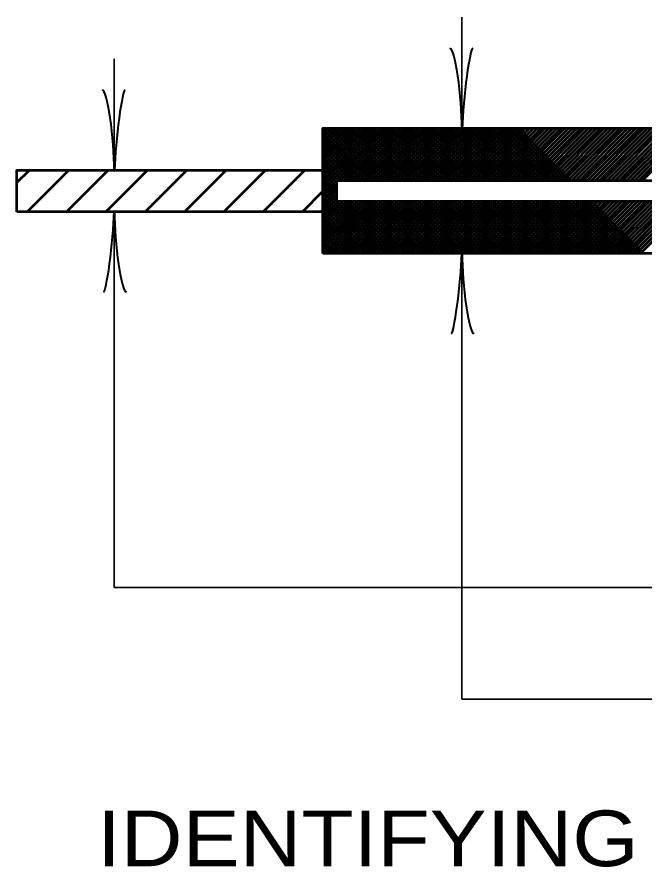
# Model space of a CAD drawing. Extents: x -1 to 679, y 0 to 440.
# Drawn here: x 282.9 to 305.44, y 121.26 to 151.8 of the extents above; entities that cross this region are included whole.
import ezdxf

# ---------------------------------------------------------------- set-up
doc = ezdxf.new("R2010")
doc.units = 0
doc.header["$LTSCALE"] = 0.8
doc.layers.add('1', color=7, linetype='Continuous', lineweight=53)

msp = doc.modelspace()

# ---------------------------------------------------------------- linework, layer by layer
at = {"layer": '1', "lineweight": 35}
for p, q in [((298.8991, 147.8013), (298.8991, 151.8013)), ((286.3991, 146.3013), (286.3991, 150.3013)), ((286.3991, 144.8013), (286.3991, 131.3013)), ((298.8991, 143.3013), (298.8991, 127.2931)), ((286.3991, 131.3013), (339.8991, 131.3013)), ((298.8991, 127.2931), (328.9684, 127.2931))]:
    msp.add_line(p, q, dxfattribs=at)
at = {"layer": '1'}
for p, q in [((293.8991, 143.3013), (293.8991, 147.8013)), ((293.8991, 147.7248), (293.9756, 147.8013)), ((293.8991, 147.5834), (294.117, 147.8013)), ((293.8991, 147.442), (294.2584, 147.8013)), ((293.8991, 147.3006), (294.3998, 147.8013)), ((293.8991, 147.1592), (294.5412, 147.8013)), ((293.8991, 147.0178), (294.6827, 147.8013)), ((293.8991, 146.8763), (294.8241, 147.8013)), ((293.8991, 146.7349), (294.9655, 147.8013)), ((293.8991, 146.5935), (295.1069, 147.8013)), ((293.8991, 146.452), (295.2484, 147.8013)), ((293.8991, 146.3106), (295.3898, 147.8013)), ((293.8991, 146.1692), (295.5312, 147.8013)), ((293.8991, 146.0277), (295.6727, 147.8013)), ((293.8991, 145.8863), (295.8141, 147.8013)), ((293.8991, 145.7449), (295.9555, 147.8013)), ((293.8991, 145.6035), (296.0969, 147.8013)), ((293.8991, 145.4621), (296.2383, 147.8013)), ((295.7336, 145.9263), (293.8991, 147.7608)), ((295.5922, 145.9263), (293.8991, 147.6194)), ((295.875, 145.9263), (294, 147.8013)), ((296.0165, 145.9263), (294.1415, 147.8013)), ((296.1579, 145.9263), (294.2829, 147.8013)), ((296.2993, 145.9263), (294.4243, 147.8013)), ((294.5048, 145.9263), (296.3798, 147.8013)), ((296.4407, 145.9263), (294.5657, 147.8013)), ((294.6462, 145.9263), (296.5212, 147.8013)), ((296.5822, 145.9263), (294.7072, 147.8013)), ((294.7876, 145.9263), (296.6626, 147.8013)), ((296.7236, 145.9263), (294.8486, 147.8013)), ((294.929, 145.9263), (296.804, 147.8013)), ((296.865, 145.9263), (294.99, 147.8013)), ((295.0704, 145.9263), (296.9454, 147.8013)), ((297.0064, 145.9263), (295.1314, 147.8013)), ((295.2118, 145.9263), (297.0868, 147.8013)), ((297.1478, 145.9263), (295.2728, 147.8013)), ((295.3533, 145.9263), (297.2283, 147.8013)), ((297.2892, 145.9263), (295.4142, 147.8013)), ((295.4947, 145.9263), (297.3697, 147.8013)), ((297.4307, 145.9263), (295.5557, 147.8013)), ((295.6361, 145.9263), (297.5111, 147.8013)), ((297.5721, 145.9263), (295.6971, 147.8013)), ((295.7775, 145.9263), (297.6525, 147.8013)), ((297.7135, 145.9263), (295.8385, 147.8013)), ((295.919, 145.9263), (297.794, 147.8013)), ((297.8549, 145.9263), (295.9799, 147.8013)), ((296.0604, 145.9263), (297.9354, 147.8013)), ((297.9963, 145.9263), (296.1213, 147.8013)), ((296.2018, 145.9263), (298.0768, 147.8013)), ((298.1377, 145.9263), (296.2627, 147.8013)), ((296.3433, 145.9263), (298.2183, 147.8013)), ((298.2792, 145.9263), (296.4042, 147.8013)), ((296.4847, 145.9263), (298.3597, 147.8013)), ((298.4207, 145.9263), (296.5457, 147.8013)), ((296.6261, 145.9263), (298.5011, 147.8013)), ((298.5621, 145.9263), (296.6871, 147.8013)), ((296.7675, 145.9263), (298.6425, 147.8013)), ((298.7035, 145.9263), (296.8285, 147.8013)), ((296.9089, 145.9263), (298.7839, 147.8013)), ((298.8449, 145.9263), (296.9699, 147.8013)), ((297.0503, 145.9263), (298.9253, 147.8013)), ((298.9863, 145.9263), (297.1113, 147.8013)), ((297.1918, 145.9263), (299.0668, 147.8013)), ((299.1277, 145.9263), (297.2527, 147.8013)), ((297.3332, 145.9263), (299.2082, 147.8013)), ((299.2692, 145.9263), (297.3942, 147.8013)), ((297.4746, 145.9263), (299.3496, 147.8013)), ((299.4106, 145.9263), (297.5356, 147.8013)), ((297.616, 145.9263), (299.491, 147.8013)), ((299.552, 145.9263), (297.677, 147.8013)), ((297.7574, 145.9263), (299.6324, 147.8013)), ((299.6934, 145.9263), (297.8184, 147.8013)), ((297.8988, 145.9263), (299.7738, 147.8013)), ((299.8348, 145.9263), (297.9598, 147.8013)), ((298.0403, 145.9263), (299.9153, 147.8013)), ((299.9762, 145.9263), (298.1012, 147.8013)), ((298.1817, 145.9263), (300.0567, 147.8013)), ((300.1177, 145.9263), (298.2427, 147.8013)), ((298.3231, 145.9263), (300.1981, 147.8013)), ((300.2591, 145.9263), (298.3841, 147.8013)), ((298.4646, 145.9263), (300.3396, 147.8013)), ((300.4005, 145.9263), (298.5255, 147.8013)), ((298.606, 145.9263), (300.481, 147.8013)), ((300.5419, 145.9263), (298.6669, 147.8013)), ((298.7474, 145.9263), (300.6224, 147.8013)), ((300.6833, 145.9263), (298.8083, 147.8013)), ((298.8888, 145.9263), (300.7638, 147.8013)), ((300.8247, 145.9263), (298.9497, 147.8013)), ((299.0302, 145.9263), (300.9052, 147.8013)), ((300.9663, 145.9263), (299.0913, 147.8013)), ((299.1717, 145.9263), (301.0467, 147.8013)), ((301.1077, 145.9263), (299.2327, 147.8013)), ((299.3131, 145.9263), (301.1881, 147.8013)), ((301.2491, 145.9263), (299.3741, 147.8013)), ((299.4545, 145.9263), (301.3295, 147.8013)), ((301.3905, 145.9263), (299.5155, 147.8013)), ((299.5959, 145.9263), (301.4709, 147.8013)), ((301.5319, 145.9263), (299.6569, 147.8013)), ((299.7373, 145.9263), (301.6123, 147.8013)), ((301.6733, 145.9263), (299.7983, 147.8013)), ((299.8787, 145.9263), (301.7537, 147.8013)), ((301.8148, 145.9263), (299.9398, 147.8013)), ((300.0202, 145.9263), (301.8952, 147.8013)), ((301.9562, 145.9263), (300.0812, 147.8013)), ((300.1616, 145.9263), (302.0366, 147.8013)), ((302.0976, 145.9263), (300.2226, 147.8013)), ((300.303, 145.9263), (302.178, 147.8013)), ((302.239, 145.9263), (300.364, 147.8013)), ((300.4444, 145.9263), (302.3194, 147.8013)), ((302.3804, 145.9263), (300.5054, 147.8013)), ((300.5858, 145.9263), (302.4608, 147.8013)), ((302.5218, 145.9263), (300.6468, 147.8013)), ((300.7272, 145.9263), (302.6022, 147.8013)), ((302.6633, 145.9263), (300.7883, 147.8013)), ((300.8687, 145.9263), (302.7437, 147.8013)), ((302.8047, 145.9263), (300.9297, 147.8013)), ((301.0102, 145.9263), (302.8852, 147.8013)), ((301.1516, 145.9263), (303.0266, 147.8013)), ((301.293, 145.9263), (303.168, 147.8013)), ((301.4344, 145.9263), (303.3094, 147.8013)), ((301.5758, 145.9263), (303.4508, 147.8013)), ((301.7172, 145.9263), (303.5922, 147.8013)), ((301.8587, 145.9263), (303.7337, 147.8013)), ((302.0001, 145.9263), (303.8751, 147.8013)), ((302.1415, 145.9263), (304.0165, 147.8013)), ((302.2829, 145.9263), (304.1579, 147.8013)), ((302.4243, 145.9263), (304.2993, 147.8013)), ((302.5657, 145.9263), (304.4407, 147.8013)), ((302.7072, 145.9263), (304.5822, 147.8013)), ((302.8486, 145.9263), (304.7236, 147.8013)), ((302.99, 145.9263), (304.865, 147.8013)), ((303.1314, 145.9263), (305.0064, 147.8013)), ((303.2728, 145.9263), (305.1478, 147.8013)), ((303.4143, 145.9263), (305.2893, 147.8013)), ((303.5557, 145.9263), (305.4307, 147.8013)), ((303.6972, 145.9263), (305.5722, 147.8013)), ((303.8386, 145.9263), (305.7136, 147.8013)), ((303.98, 145.9263), (305.855, 147.8013)), ((304.1214, 145.9263), (305.9964, 147.8013)), ((304.2628, 145.9263), (306.1378, 147.8013)), ((304.4042, 145.9263), (306.2792, 147.8013)), ((304.5457, 145.9263), (306.4207, 147.8013)), ((304.6871, 145.9263), (306.5621, 147.8013)), ((304.8285, 145.9263), (306.7035, 147.8013)), ((304.9699, 145.9263), (306.8449, 147.8013)), ((305.1113, 145.9263), (306.9863, 147.8013)), ((305.2527, 145.9263), (307.1277, 147.8013)), ((305.3942, 145.9263), (307.2692, 147.8013)), ((295.4507, 145.9263), (293.8991, 147.478)), ((295.3093, 145.9263), (293.8991, 147.3366)), ((295.1679, 145.9263), (293.8991, 147.1952)), ((295.0265, 145.9263), (293.8991, 147.0538)), ((294.8851, 145.9263), (293.8991, 146.9123)), ((294.7437, 145.9263), (293.8991, 146.7709)), ((294.6022, 145.9263), (293.8991, 146.6295)), ((282.8991, 145.852), (283.3484, 146.3013)), ((283.2627, 144.8013), (284.7627, 146.3013)), ((284.6768, 144.8013), (286.1768, 146.3013)), ((286.0911, 144.8013), (287.5911, 146.3013)), ((287.5053, 144.8013), (289.0053, 146.3013)), ((288.9195, 144.8013), (290.4195, 146.3013)), ((290.3338, 144.8013), (291.8338, 146.3013)), ((291.7479, 144.8013), (293.2479, 146.3013)), ((294.4608, 145.9263), (293.8991, 146.4881)), ((294.3991, 145.8467), (293.8991, 146.3467)), ((294.3991, 145.7053), (293.8991, 146.2053)), ((294.3991, 145.5638), (293.8991, 146.0638)), ((294.3991, 145.4224), (293.8991, 145.9224)), ((293.8991, 145.3207), (294.3991, 145.8207)), ((294.3991, 145.281), (293.8991, 145.781)), ((293.8991, 145.1792), (294.3991, 145.6792)), ((293.1622, 144.8013), (293.8991, 145.5383)), ((296.2373, 143.3013), (293.8991, 145.6396)), ((293.8991, 145.0378), (294.3991, 145.5378)), ((296.0959, 143.3013), (293.8991, 145.4982)), ((293.8991, 144.8964), (294.3991, 145.3964)), ((295.9544, 143.3013), (293.8991, 145.3567)), ((293.8991, 144.755), (294.3991, 145.255)), ((295.813, 143.3013), (293.8991, 145.2152)), ((293.8991, 144.6136), (294.4618, 145.1763)), ((293.8991, 144.4722), (294.6033, 145.1763)), ((293.8991, 144.3307), (294.7447, 145.1763)), ((293.8991, 144.1893), (294.8861, 145.1763)), ((293.8991, 144.0479), (295.0275, 145.1763)), ((293.8991, 143.9064), (295.169, 145.1763)), ((293.8991, 143.765), (295.3104, 145.1763)), ((293.8991, 143.6236), (295.4518, 145.1763)), ((293.8991, 143.4822), (295.5933, 145.1763)), ((293.8991, 143.3407), (295.7347, 145.1763)), ((295.6716, 143.3013), (293.8991, 145.0738)), ((294.0011, 143.3013), (295.8761, 145.1763)), ((294.1425, 143.3013), (296.0175, 145.1763)), ((294.2839, 143.3013), (296.1589, 145.1763)), ((294.4253, 143.3013), (296.3003, 145.1763)), ((296.3787, 143.3013), (294.5037, 145.1763)), ((294.5668, 143.3013), (296.4418, 145.1763)), ((296.5202, 143.3013), (294.6452, 145.1763)), ((294.7082, 143.3013), (296.5832, 145.1763)), ((296.6616, 143.3013), (294.7866, 145.1763)), ((294.8496, 143.3013), (296.7246, 145.1763)), ((296.803, 143.3013), (294.928, 145.1763)), ((294.991, 143.3013), (296.866, 145.1763)), ((296.9444, 143.3013), (295.0694, 145.1763)), ((295.1324, 143.3013), (297.0074, 145.1763)), ((297.0858, 143.3013), (295.2108, 145.1763)), ((295.2738, 143.3013), (297.1488, 145.1763)), ((297.2272, 143.3013), (295.3522, 145.1763)), ((295.4153, 143.3013), (297.2903, 145.1763)), ((297.3687, 143.3013), (295.4937, 145.1763)), ((295.5567, 143.3013), (297.4317, 145.1763)), ((297.5101, 143.3013), (295.6351, 145.1763)), ((295.6981, 143.3013), (297.5731, 145.1763)), ((297.6515, 143.3013), (295.7765, 145.1763)), ((295.8396, 143.3013), (297.7146, 145.1763)), ((297.7929, 143.3013), (295.9179, 145.1763)), ((295.981, 143.3013), (297.856, 145.1763)), ((297.9343, 143.3013), (296.0593, 145.1763)), ((296.1224, 143.3013), (297.9974, 145.1763)), ((298.0757, 143.3013), (296.2007, 145.1763)), ((296.2638, 143.3013), (298.1388, 145.1763)), ((298.2172, 143.3013), (296.3422, 145.1763)), ((296.4052, 143.3013), (298.2802, 145.1763)), ((298.3586, 143.3013), (296.4836, 145.1763)), ((296.5467, 143.3013), (298.4217, 145.1763)), ((298.5, 143.3013), (296.625, 145.1763)), ((296.6881, 143.3013), (298.5631, 145.1763)), ((298.6415, 143.3013), (296.7665, 145.1763)), ((296.8295, 143.3013), (298.7045, 145.1763)), ((298.7829, 143.3013), (296.9079, 145.1763)), ((296.9709, 143.3013), (298.8459, 145.1763)), ((298.9243, 143.3013), (297.0493, 145.1763)), ((297.1123, 143.3013), (298.9873, 145.1763)), ((299.0657, 143.3013), (297.1907, 145.1763)), ((297.2537, 143.3013), (299.1287, 145.1763)), ((299.2072, 143.3013), (297.3322, 145.1763)), ((297.3952, 143.3013), (299.2702, 145.1763)), ((299.3486, 143.3013), (297.4736, 145.1763)), ((297.5366, 143.3013), (299.4116, 145.1763)), ((299.49, 143.3013), (297.615, 145.1763)), ((297.678, 143.3013), (299.553, 145.1763)), ((299.6314, 143.3013), (297.7564, 145.1763)), ((297.8194, 143.3013), (299.6944, 145.1763)), ((299.7728, 143.3013), (297.8978, 145.1763)), ((297.9608, 143.3013), (299.8358, 145.1763)), ((299.9142, 143.3013), (298.0392, 145.1763)), ((298.1022, 143.3013), (299.9772, 145.1763)), ((300.0557, 143.3013), (298.1807, 145.1763)), ((298.2437, 143.3013), (300.1187, 145.1763)), ((300.1971, 143.3013), (298.3221, 145.1763)), ((298.3852, 143.3013), (300.2602, 145.1763)), ((300.3385, 143.3013), (298.4635, 145.1763)), ((298.5266, 143.3013), (300.4016, 145.1763)), ((300.4799, 143.3013), (298.6049, 145.1763)), ((298.668, 143.3013), (300.543, 145.1763)), ((300.6213, 143.3013), (298.7463, 145.1763)), ((298.8094, 143.3013), (300.6844, 145.1763)), ((300.7627, 143.3013), (298.8877, 145.1763)), ((298.9508, 143.3013), (300.8258, 145.1763)), ((300.9042, 143.3013), (299.0292, 145.1763)), ((299.0922, 143.3013), (300.9672, 145.1763)), ((301.0457, 143.3013), (299.1707, 145.1763)), ((299.2337, 143.3013), (301.1087, 145.1763)), ((301.1871, 143.3013), (299.3121, 145.1763)), ((299.3751, 143.3013), (301.2501, 145.1763)), ((301.3285, 143.3013), (299.4535, 145.1763)), ((299.5165, 143.3013), (301.3915, 145.1763)), ((301.4699, 143.3013), (299.5949, 145.1763)), ((299.6579, 143.3013), (301.5329, 145.1763)), ((301.6113, 143.3013), (299.7363, 145.1763)), ((299.7993, 143.3013), (301.6743, 145.1763)), ((301.7527, 143.3013), (299.8777, 145.1763)), ((299.9407, 143.3013), (301.8157, 145.1763)), ((301.8942, 143.3013), (300.0192, 145.1763)), ((300.0822, 143.3013), (301.9572, 145.1763)), ((302.0356, 143.3013), (300.1606, 145.1763)), ((300.2236, 143.3013), (302.0986, 145.1763)), ((302.177, 143.3013), (300.302, 145.1763)), ((300.365, 143.3013), (302.24, 145.1763)), ((302.3184, 143.3013), (300.4434, 145.1763)), ((300.5064, 143.3013), (302.3814, 145.1763)), ((302.4598, 143.3013), (300.5848, 145.1763)), ((300.6478, 143.3013), (302.5228, 145.1763)), ((302.6012, 143.3013), (300.7262, 145.1763)), ((300.7893, 143.3013), (302.6643, 145.1763)), ((302.7427, 143.3013), (300.8677, 145.1763)), ((300.9307, 143.3013), (302.8057, 145.1763)), ((302.8841, 143.3013), (301.0091, 145.1763)), ((301.0722, 143.3013), (302.9472, 145.1763)), ((303.0255, 143.3013), (301.1505, 145.1763)), ((301.2136, 143.3013), (303.0886, 145.1763)), ((303.1669, 143.3013), (301.2919, 145.1763)), ((301.355, 143.3013), (303.23, 145.1763)), ((303.3083, 143.3013), (301.4333, 145.1763)), ((301.4964, 143.3013), (303.3714, 145.1763)), ((303.4497, 143.3013), (301.5747, 145.1763)), ((301.6378, 143.3013), (303.5128, 145.1763)), ((303.5913, 143.3013), (301.7163, 145.1763)), ((301.7792, 143.3013), (303.6542, 145.1763)), ((303.7327, 143.3013), (301.8577, 145.1763)), ((301.9207, 143.3013), (303.7957, 145.1763)), ((303.8741, 143.3013), (301.9991, 145.1763)), ((302.0621, 143.3013), (303.9371, 145.1763)), ((304.0155, 143.3013), (302.1405, 145.1763)), ((302.2035, 143.3013), (304.0785, 145.1763)), ((304.1569, 143.3013), (302.2819, 145.1763)), ((302.3449, 143.3013), (304.2199, 145.1763)), ((304.2983, 143.3013), (302.4233, 145.1763)), ((302.4863, 143.3013), (304.3613, 145.1763)), ((304.4398, 143.3013), (302.5648, 145.1763)), ((302.6277, 143.3013), (304.5027, 145.1763)), ((304.5812, 143.3013), (302.7062, 145.1763)), ((302.7692, 143.3013), (304.6442, 145.1763)), ((304.7226, 143.3013), (302.8476, 145.1763)), ((302.9106, 143.3013), (304.7856, 145.1763)), ((304.864, 143.3013), (302.989, 145.1763)), ((303.052, 143.3013), (304.927, 145.1763)), ((305.0054, 143.3013), (303.1304, 145.1763)), ((303.1934, 143.3013), (305.0684, 145.1763)), ((305.1468, 143.3013), (303.2718, 145.1763)), ((303.3349, 143.3013), (305.2099, 145.1763)), ((305.2883, 143.3013), (303.4133, 145.1763)), ((303.4763, 143.3013), (305.3513, 145.1763)), ((305.4297, 143.3013), (303.5547, 145.1763)), ((303.6178, 143.3013), (305.4928, 145.1763)), ((303.7592, 143.3013), (305.6342, 145.1763)), ((303.9006, 143.3013), (305.7756, 145.1763)), ((304.042, 143.3013), (305.917, 145.1763)), ((304.1834, 143.3013), (306.0584, 145.1763)), ((304.3248, 143.3013), (306.1998, 145.1763)), ((304.4663, 143.3013), (306.3413, 145.1763)), ((304.6077, 143.3013), (306.4827, 145.1763)), ((304.7491, 143.3013), (306.6241, 145.1763)), ((304.8905, 143.3013), (306.7655, 145.1763)), ((305.0319, 143.3013), (306.9069, 145.1763)), ((305.1733, 143.3013), (307.0483, 145.1763)), ((305.3148, 143.3013), (307.1898, 145.1763)), ((293.8991, 144.8013), (282.8991, 144.8013)), ((295.5302, 143.3013), (293.8991, 144.9324)), ((295.3888, 143.3013), (293.8991, 144.791)), ((295.2473, 143.3013), (293.8991, 144.6496)), ((295.1059, 143.3013), (293.8991, 144.5082)), ((294.9645, 143.3013), (293.8991, 144.3667)), ((294.8231, 143.3013), (293.8991, 144.2253)), ((294.6817, 143.3013), (293.8991, 144.0839)), ((294.5403, 143.3013), (293.8991, 143.9425)), ((294.3988, 143.3013), (293.8991, 143.8011)), ((294.2574, 143.3013), (293.8991, 143.6597)), ((294.116, 143.3013), (293.8991, 143.5182)), ((293.9746, 143.3013), (293.8991, 143.3768))]:
    msp.add_line(p, q, dxfattribs=at)
for points in [[(293.8991, 143.3013), (293.8991, 147.8013), (318.3991, 147.8013), (318.8991, 148.8013), (329.3991, 148.8013), (330.3991, 147.0513), (329.8991, 147.0513), (329.8991, 147.3013), (328.8991, 147.3013), (328.8991, 147.8013), (318.8991, 147.8013), (318.8991, 143.3013), (328.8991, 143.3013), (328.8991, 143.8013), (329.8991, 143.8013), (329.8991, 144.0513), (330.3991, 144.0513), (329.3991, 142.3013), (318.8991, 142.3013), (318.3991, 143.3013)], [(293.8991, 143.3013), (293.8991, 147.8013), (318.3991, 147.8013), (318.8991, 148.8013), (329.3991, 148.8013), (330.3991, 147.0513), (329.8991, 147.0513), (329.8991, 147.3013), (328.8991, 147.3013), (328.8991, 147.8013), (318.8991, 147.8013), (318.8991, 143.3013), (328.8991, 143.3013), (328.8991, 143.8013), (329.8991, 143.8013), (329.8991, 144.0513), (330.3991, 144.0513), (329.3991, 142.3013), (318.8991, 142.3013), (318.3991, 143.3013)], [(318.3991, 145.1763), (294.3991, 145.1763), (294.3991, 145.9263), (318.3991, 145.9263)], [(294.3991, 145.9263), (318.3991, 145.9263), (318.3991, 145.1763), (294.3991, 145.1763)], [(294.3991, 145.1763), (294.3991, 145.9263), (318.3991, 145.9263), (318.3991, 145.1763)]]:
    msp.add_lwpolyline(points, close=True, dxfattribs=at)
for points in [[(298.8991, 147.8013), (318.3991, 147.8013), (318.8991, 148.8013), (329.3991, 148.8013), (330.3991, 147.0513), (329.8991, 147.0513), (329.8991, 147.3013), (328.8991, 147.3013), (328.8991, 147.8013), (318.8991, 147.8013), (318.8991, 143.3013), (328.8991, 143.3013), (328.8991, 143.8013), (329.8991, 143.8013), (329.8991, 144.0513), (330.3991, 144.0513), (329.3991, 142.3013), (318.8991, 142.3013), (318.3991, 143.3013), (293.8991, 143.3013)], [(282.8991, 144.8013), (282.8991, 146.3013), (293.8991, 146.3013)]]:
    msp.add_lwpolyline(points, dxfattribs=at)
at = {"layer": '1', "lineweight": 40}
for centre, major_axis, ratio, start_param, end_param in [((298.6228, 148.8925), (0.1562, -1.7857), 0.122415, 0.8963533, 3.1415927), ((299.1107, 148.9218), (-0.1757, -1.7565), 0.07063, 3.1407148, 5.41811), ((286.1228, 147.3925), (0.1562, -1.7857), 0.122415, 0.8963533, 3.1415927), ((286.6107, 147.4218), (-0.1757, -1.7565), 0.07063, 3.1407148, 5.41811), ((286.1875, 143.6808), (0.1757, 1.7565), 0.07063, 3.1407148, 5.41811), ((286.1875, 143.6808), (0.1757, 1.7565), 0.07063, 3.1407148, 5.41811), ((286.6754, 143.7101), (-0.1562, 1.7857), 0.122415, 0.8963533, 3.1415927), ((286.6754, 143.7101), (-0.1562, 1.7857), 0.122415, 0.8963533, 3.1415927), ((298.6875, 142.1808), (0.1757, 1.7565), 0.07063, 3.1407148, 5.41811), ((298.6875, 142.1808), (0.1757, 1.7565), 0.07063, 3.1407148, 5.41811), ((299.1754, 142.2101), (-0.1562, 1.7857), 0.122415, 0.8963533, 3.1415927), ((299.1754, 142.2101), (-0.1562, 1.7857), 0.122415, 0.8963533, 3.1415927)]:
    msp.add_ellipse(centre, major_axis=major_axis, ratio=ratio, start_param=start_param, end_param=end_param, dxfattribs=at)

# ---------------------------------------------------------------- texts
at = {"layer": '1', "width": 1.15}
msp.add_text('IDENTIFYING SYMBOLS V', height=2, dxfattribs=at).set_placement((285.7758, 121.2906))

doc.saveas('drawing.dxf')
